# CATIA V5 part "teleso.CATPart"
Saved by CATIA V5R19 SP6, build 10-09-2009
Part number: teleso
Bounding box of the stored display mesh (mm): x -19.36 to 19.36, y -13.147 to 13.147, z 0 to 5
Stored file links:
  D:\DURATEC\teleso.CATPart
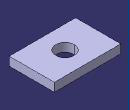
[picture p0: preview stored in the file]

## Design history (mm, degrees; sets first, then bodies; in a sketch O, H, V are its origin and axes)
Body1 (main body)
  Sketch1 on xy-plane, origin (0, 0, 0), H (1, 0, 0), V (0, 1, 0)
    line L1 (19.3604, 13.1467) -> (19.3604, -13.1467)
    line L2 (19.3604, -13.1467) -> (-19.3604, -13.1467)
    line L3 (-19.3604, -13.1467) -> (-19.3604, 13.1467)
    line L4 (-19.3604, 13.1467) -> (19.3604, 13.1467)
    circle A1 centre (0, 0) radius 5.4266
    vertical: L1 V, L3 V
    horizontal: L2 H, L4 H
    equidistance: L1 L3 O, L2 L4 O
  Pad1: profile Sketch1, direction (0, 0, 1), length 5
